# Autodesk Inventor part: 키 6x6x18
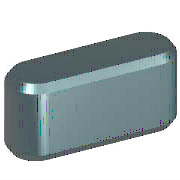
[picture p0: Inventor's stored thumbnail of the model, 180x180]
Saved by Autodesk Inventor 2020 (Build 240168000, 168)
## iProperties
IsCustomPart: 0
Created: 2012-02
Part Number: 키 6x6x18
Material: 강철, 연강
Document SubType Name: Modeling
Standard: JIS B 1301
Designer: mdu
Standards Organization: JIS
Language: ko-KR
Size Designation: 6x6x18
Categories: <MemberInstance><Categories><Category DisplayName="샤프트 부품" InternalName="7f7aeb1f-a693-4053-b835-cee3144e0d98" Mnemonic="SHFT"><Category DisplayName="키" Interna
Density: 1 g/cm^3
Appearance: 보라색
Author: mdu
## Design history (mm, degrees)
workplane "Work Plane1"
workplane "Work Plane2"
sketch "스케치1"
  geometry: L1 (3, 3)-(15, 3); L2 (15, -3)-(3, -3); L3 (0, 9.4)-(0, -7.4) reference; L4 (-5, 0)-(30, 0) reference; L5 (18, 0)-(18, 7); A1 r 3 centre (3, 0) between (3, 3) and (3, -3); A2 r 3 centre (15, 0) between (15, -3) and (15, 3)
  constraints: 6 end point, 5 point on circle, 4 tangent, 3 point on line, 2 centre point, 1 horizontal, 1 parallel, 1 perpendicular
  dimensions: "d0" = 3 radius of A1 (= 0.5 x PB); "d13" = 3 radius of A2 (= 0.5 x PB); "d14" = 18 distance between parallel lines of L5 L3 (= NLG)
extrude "본체1" new body sketch "스케치1" taper "d3" = 0 deg; stored distance "d4" = 10
workplane "Work Plane3"
body "Solid1"
chamfer "모따기1" distance "d8" = 0.4 (= PHH); stored, may be unused: second distance "d9" = 0.4 (= PHH), angle "d15" = 45 deg
other parameters: "d1" = -3.5 (= -PNT), "d2" = 2.5 (= PH - PNT), "NLG" = 18 [user parameter; used in 3 equation terms], "PB" = 6 [user parameter; used in 2 equation terms], "PNT" = 3.5 [user parameter; used in 2 equation terms], "PH" = 6 [user parameter; used in 1 equation term], "PHH" = 0.4 [user parameter; used in 2 equation terms], "d10" = 0, "d16" = 0, "d17" = 0, "d18" = 0, "WDMIN" = 17 [user parameter], "PLB2" = 18 (= NLG) [user parameter], "WDMAX" = 22 [user parameter], "PLB1" = 18 (= NLG) [user parameter], "RR" = 0.16 [user parameter], "PUEB" = 2.8 [user parameter]
